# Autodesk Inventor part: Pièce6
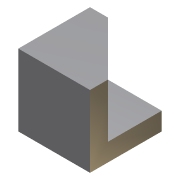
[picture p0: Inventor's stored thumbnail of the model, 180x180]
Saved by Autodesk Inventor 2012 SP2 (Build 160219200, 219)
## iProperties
Created: 2013-10
Part Number: Pièce6
Material: Default
Document SubType Name: Modeling
Designer: papa
Density: 1 g/cm^3
Author: papa
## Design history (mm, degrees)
sketch "Esquisse1"
  geometry: L1 (-10, 10)-(10, 10); L2 (10, 10)-(10, -10); L3 (10, -10)-(-10, -10); L4 (-10, -10)-(-10, 10); L5 (0, 0)-(0, 16.788); L6 (0, 0)-(20.494, 0)
  constraints: 12 end point, 3 parallel, 2 perpendicular, 1 horizontal, 1 other
  dimensions: "d0" = 20 distance of L1.start L1.end; "d1" = 20 distance of L3.end L1.start; "d2" = 10 distance between parallel lines of L4 L5 (= 0.5 x d0)
extrude "Extrusion1" new body sketch "Esquisse1" distance "d3" = 20; taper "d4" = 0 deg
sketch "Esquisse2"
  geometry: L1 (-20, 20)-(-20, 0) reference; L2 (0, 20)-(-20, 20) reference; L3 (-15, 20)-(-5, 20); L4 (-5, 20)-(-5, 5); L5 (-5, 5)-(-15, 5); L6 (-15, 5)-(-15, 20); 1 further point
  constraints: 8 end point, 2 parallel, 1 horizontal, 1 perpendicular, 1 point on line
  dimensions: "d5" = 10 distance of L3.start L3.end; "d6" = 5 distance between parallel lines of L6 L1; "d7" = 15 distance of L5.end L3.start
extrude "Extrusion2" cut sketch "Esquisse2" stored distance "d8" = 20; taper "d9" = 0 deg
chamfer "Chanfrein1" distance "d10" = 15; stored, may be unused: second distance "d11" = 2, angle "d12" = 45 deg
node "Solide1"
